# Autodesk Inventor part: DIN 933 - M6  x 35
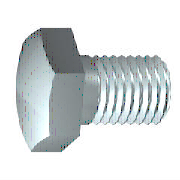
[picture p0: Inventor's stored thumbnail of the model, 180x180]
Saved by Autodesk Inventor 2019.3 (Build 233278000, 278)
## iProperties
Created: 2018-01
Part Number: DIN 933 - M6  x 35
Material: Ocel, měkká
Description: Šestihranný šroub
Document SubType Name: Modeling
Standard: DIN 933
Designer: B-hon
Standards Organization: DIN
Language: cs-CZ
Size Designation: M6  x 35
Categories: <MemberInstance><Categories><Category DisplayName="Spojovací materiál" InternalName="e4da775c-781d-43d5-af7c-5136215cf5a6" Mnemonic="FSTN"><Category DisplayName
Density: 7.85 g/cm^3
Appearance: Pololeštěná
IsCustomPart: 0
Author: B-hon
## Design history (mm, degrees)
sketch "Náčrt1"
  geometry: L1 (0, 4.35)-(0, 2.729); L2 (3, 3)-(35, 3); L3 (35, 3)-(35, 0); L4 (35, 0)-(-0.5, 0); L5 (-7.6, 0)-(42.1, 0) reference; L6 (-0.5, 0)-(-0.5, 4.35); L7 (-0.5, 4.35)-(0, 4.35); L8 (3, 3)-(2.386, 2.729); L9 (2.386, 2.729)-(0, 2.729); L10 (0, -0.87)-(0, 5.22) reference
  constraints: 16 end point, 2 collinear, 2 perpendicular, 1 parallel
  dimensions: "d0" = 35 distance between parallel lines of L3 L1 (= NLG); "d1" = 32 distance from line of L2.start L3 (= GEL); "d2" = 6 diameter of L2 L4 (= GD); "d9" = 0.5001 distance between parallel lines of L6 L1 (computed from SD); "d10" = 8.7 diameter of L7 L4 (= SD2); "d13" = 0.61355 horizontal distance of L2.start L8.end (computed from GAL); "d14" = 5.45873 diameter of L9 L4 (= BDM)
revolve "Těleso" sketch "Náčrt1" stored, may be unused: angle "d12" = 90 deg
sketch "Náčrt2"
  geometry: L1 (0, 5.774)-(5, 2.887); L2 (5, 2.887)-(5, -2.887); L3 (5, -2.887)-(0, -5.774); L4 (0, -5.774)-(-5, -2.887); L5 (-5, -2.887)-(-5, 2.887); L6 (-5, 2.887)-(0, 5.774); 2 further points
  constraints: 12 end point, 1 coincident, 1 vertical, 11 other
  dimensions: "d11" = 10 distance between parallel lines of L5 L2 (= SW)
extrude "Hlava" join sketch "Náčrt2" distance "d3" = 3.5 (= KOH - SD); taper "d4" = 0 deg
sketch "Náčrt4"
  geometry: L1 (-4, 5)-(-4, 5.774); L2 (-4, 5.774)-(-3.554, 5.774); L3 (-3.554, 5.774)-(-4, 5); L4 (-4.7, 0)-(0.2, 0) reference; L5 (-0.5, 5.774)-(-4, 5.774) reference; L6 (-4, 2.887)-(-4, 5.774) reference
  constraints: 6 end point, 2 collinear, 1 perpendicular, 1 vertical
  dimensions: "d5" = 30 deg angle of L3 L1 (= ANG1); "d19" = 10 diameter of L1.start L4 (= SW0)
revolve "Zkosení1" sketch "Náčrt4" stored, may be unused: angle "d21" = 90 deg
workplane "Work Plane1"
body "Solid1"
feature "Závit" dims "d15" = 32 (= GEL), "d16" = 0
chamfer "Zkosení2" distance "d6" = 0.61345 (= -0.5 x SPD + 0.5 x GD); stored, may be unused: second distance "d7" = 0.61355 (computed from GUL), angle "d55" = 45 deg
other parameters: "NLG" = 35 [user parameter; used in 1 equation term], "GD" = 6 (= NND) [user parameter; used in 2 equation terms], "BDM" = 5.45873 [user parameter; used in 1 equation term], "KOH" = 4 [user parameter; used in 1 equation term], "GEL" = 32 [user parameter; used in 2 equation terms], "SW" = 10 [user parameter; used in 2 equation terms], "SW0" = 10 [user parameter; used in 1 equation term], "SPD" = 4.7731 (= NND - 1.2269 x PTC) [user parameter; used in 1 equation term], "SD2" = 8.7 [user parameter; used in 1 equation term], "SD" = 0.5 [user parameter; used in 2 equation terms], "ANG1" = 30 deg [user parameter; used in 1 equation term], "GAL" = 0.61345 (= 0.61345 x PTC) [user parameter; used in 1 equation term], "GUL" = 0.61345 (= 0.61345 x PTC) [user parameter; used in 1 equation term], "d8" = 0, "RR" = 0.25 [user parameter], "d57" = 0, "d58" = 0, "GD1" = 4.7731 (= THREADDIA - 1.2269 x PTC) [user parameter], "THREADDIA" = 6 [user parameter; used in 1 equation term], "TOA" = 30 deg [user parameter], "PTC" = 1 [user parameter; used in 5 equation terms], "NND" = 6 [user parameter; used in 2 equation terms], "E0" = 11.55 (= 1.155 x SW) [user parameter]
